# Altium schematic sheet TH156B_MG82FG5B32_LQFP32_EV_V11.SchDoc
size 279 x 203 mm; PageSetup: Record=PageOptions|CenterHorizontal=True|CenterVertical=True|PrintScale=0.98|XCorrection=1.00|YCorrection=1.00|PrintKind=0|BorderSize=5000000|LeftOffset=0|BottomOffset=0|Orientation=2|PaperLength=1000|PaperWidth=1000|Scale=100|PaperSource=7|PrintQuality=-4|MediaType=1|DitherType=10|PaperKind=A4 (210 x 297 mm)|PrintScaleMode=1
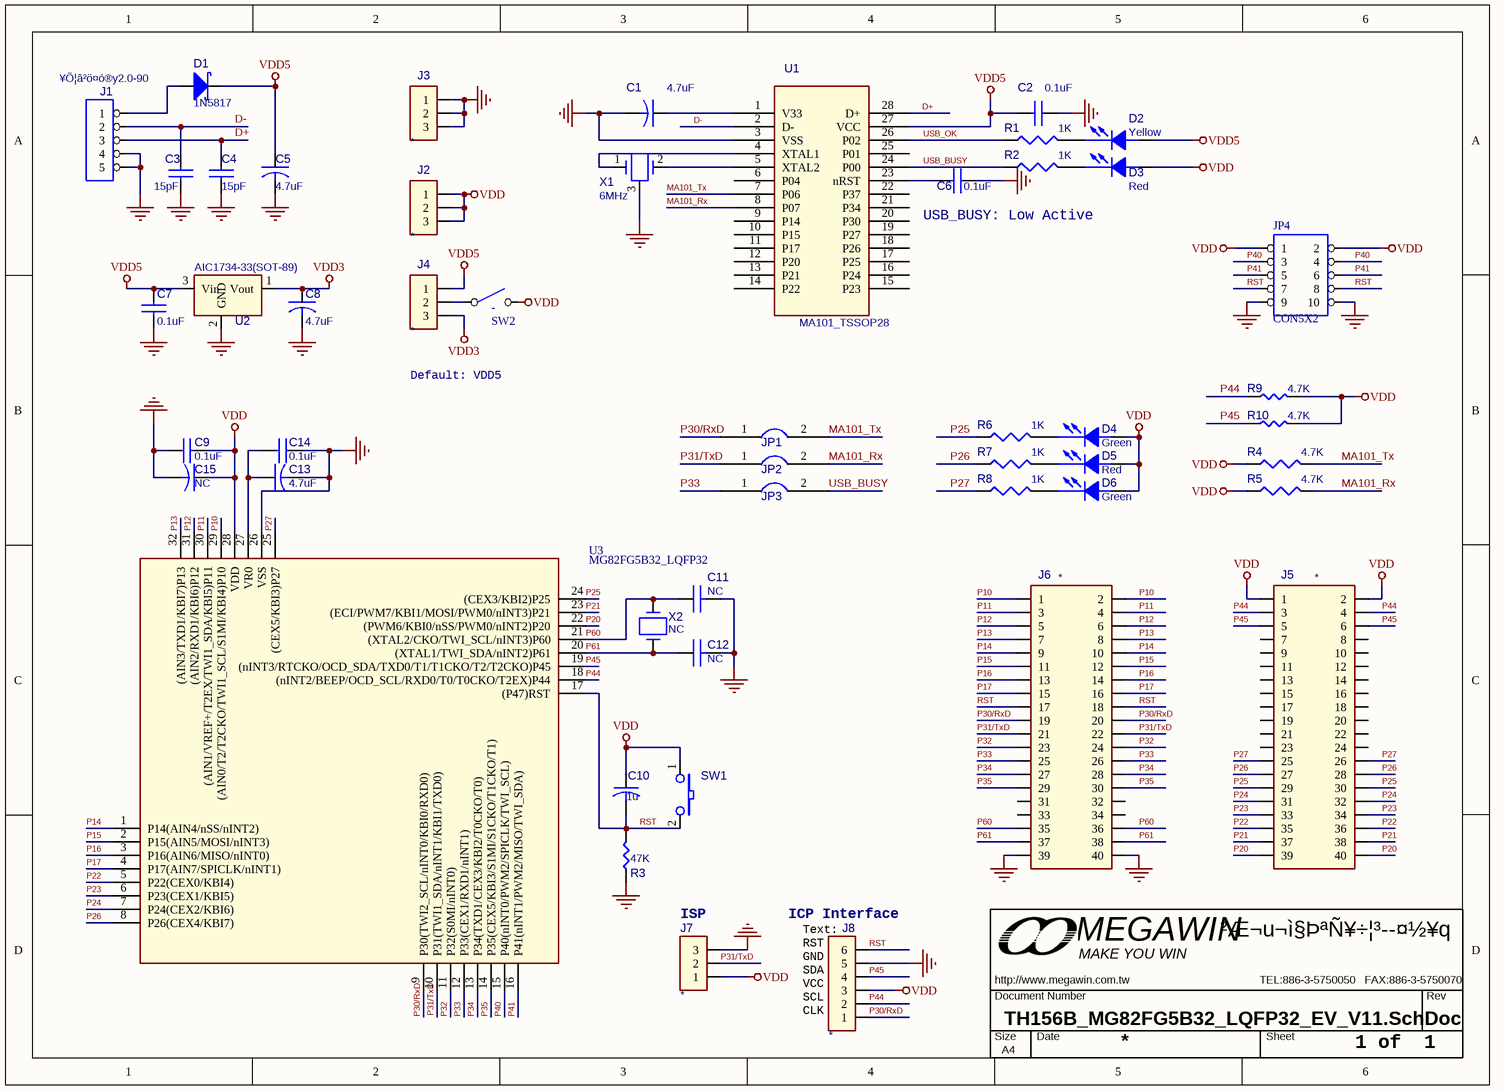
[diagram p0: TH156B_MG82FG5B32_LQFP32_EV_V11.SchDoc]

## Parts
C1  4.7uF  [0805C]
C2  0.1uF  [0805C]
C3  15pF  [0805C]
C4  15pF  [0805C]
C5  4.7uF  [1206C]
C6  0.1uF  [0805C]
C7  0.1uF  [0805C]
C8  4.7uF  [0805C]
C9  0.1uF  [0805C]
C10  1u  [0805C]
C11  NC  [0805C]
C12  NC  [0805C]
C13  4.7uF  [0805C]
C14  0.1uF  [0805C]
C15  NC  [0805C]
D1  1N5817  [D5817_SMD_1]
D2  Yellow  [0805D]
D3  Red  [0805D]
D4  Green  [0805D]
D5  Red  [0805D]
D6  Green  [0805D]
J1  ¥Õ¦â²ö¤ó®y2.0-90  [PC5p200_90]
J2  *  [PS3P254]
J3  *  [PS3P254]
J4  *  [JUMP3_SMD]
J5  *  [PS20X2P254]
J6  *  [PS20X2P254]
J7  *  [PS3P254f_90]
J8  *  [PS6P254F_90]
JP1  JUMPER2  [PS2P254]  (value not drawn)
JP2  JUMPER2  [PS2P254]  (value not drawn)
JP3  JUMPER2  [PS2P254]  (value not drawn)
JP4  CON5X2  [PS5X2P254]
MW1  OrgName: ²Æ¬u¬ì§ÞªÑ¥÷¦³­­¤½¥q  OrgAddr1: MEGAWIN  OrgAddr3: TEL:886-3-5750050   FAX:886-3-5750070  Page Size: A4  [MEGAWIN_T]  (hidden comment: MW-A4)  (no BOM)
R1  1K  [0805R]
R2  1K  [0805R]
R3  47K  [0805R]
R4  4.7K  [0805R]
R5  4.7K  [0805R]
R6  1K  [0805R]
R7  1K  [0805R]
R8  1K  [0805R]
R9  4.7K  [0805R]
R10  4.7K  [0805R]
SW1  SW TACT-SPST  [SW_T_2P]  (value not drawn)
SW2  -  [DIP2_SW]
U1  MA101_TSSOP28  [SSOP28_220P065]
U2  AIC1734-33(SOT-89)  [SOT89]
U3  MG82FG5B32_LQFP32  [QFP32_7X7p080]
X1  6MHz  [X3P]
X2  NC  [X49U]

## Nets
GND_POWER: C1.2 C2.1 C3.2 C4.2 C5.2 C6.1 C7.2 C8.2 C9.1 C11.2 C12.2 C13.2 C14.1 C15.2 J1.4 J1.5 J3.1 J3.2 J3.3 J6.39 J6.40 J7.3 J8.5 JP4.9 JP4.10 R3.1 U1.3(VSS) U2.2(GND) U3.26(VSS) X1.3
VDD: C9.2 C10.1(POS) C15.1 D3.1(ANODE) D4.1(ANODE) D5.1(ANODE) D6.1(ANODE) J2.1 J2.2 J2.3 J5.1 J5.2 J7.1 J8.3 JP4.1 JP4.2 R4.1 R5.1 R9.2 R10.2 SW1.1 SW2.2(NO) U3.28(VDD)
VDD3: C8.1 J4.3 U2.1(Vout)
VDD5: C2.2 C5.1 C7.1 D1.2(K) D2.1(ANODE) J4.1 U1.27(VCC) U2.3(Vin)
D+: C4.1 J1.3 U1.28(D+)
D-: C3.1 J1.2 U1.2(D-)
MA101_Rx: JP2.2 R5.2 U1.8(P07)
MA101_Tx: JP1.2 R4.2 U1.7(P06)
P10: J6.1 J6.2 U3.29((AIN0/T2/T2CKO/TWI1_SCL/S1MI/KBI4)P10)
P11: J6.3 J6.4 U3.30((AIN1/VREF+/T2EX/TWI1_SDA/KBI5)P11)
P12: J6.5 J6.6 U3.31((AIN2/RXD1/KBI6)P12)
P13: J6.7 J6.8 U3.32((AIN3/TXD1/KBI7)P13)
P14: J6.9 J6.10 U3.1(P14(AIN4/nSS/nINT2))
P15: J6.11 J6.12 U3.2(P15(AIN5/MOSI/nINT3))
P16: J6.13 J6.14 U3.3(P16(AIN6/MISO/nINT0))
P17: J6.15 J6.16 U3.4(P17(AIN7/SPICLK/nINT1))
P20: J5.39 J5.40 U3.22((PWM6/KBI0/nSS/PWM0/nINT2)P20)
P21: J5.37 J5.38 U3.23((ECI/PWM7/KBI1/MOSI/PWM0/nINT3)P21)
P22: J5.35 J5.36 U3.5(P22(CEX0/KBI4))
P23: J5.33 J5.34 U3.6(P23(CEX1/KBI5))
P24: J5.31 J5.32 U3.7(P24(CEX2/KBI6))
P25: J5.29 J5.30 R6.1 U3.24((CEX3/KBI2)P25)
P26: J5.27 J5.28 R7.1 U3.8(P26(CEX4/KBI7))
P27: J5.25 J5.26 R8.1 U3.25((CEX5/KBI3)P27)
P30/RxD: J6.19 J6.20 J8.1 JP1.1 U3.9(P30(TWI2_SCL/nINT0/KBI0/RXD0))
P31/TxD: J6.21 J6.22 J7.2 JP2.1 U3.10(P31(TWI1_SDA/nINT1/KBI1/TXD0))
P32: J6.23 J6.24 U3.11(P32(S0MI/nINT0))
P33: J6.25 J6.26 JP3.1 U3.12(P33(CEX1/RXD1/nINT1))
P34: J6.27 J6.28 U3.13(P34(TXD1/CEX3/KBI2/T0CKO/T0))
P35: J6.29 J6.30 U3.14(P35(CEX5/KBI3/S1MI/S1CKO/T1CKO/T1))
P40: JP4.3 JP4.4 U3.15(P40(nINT0/PWM2/SPICLK/TWI_SCL))
P41: JP4.5 JP4.6 U3.16(P41(nINT1/PWM2/MISO/TWI_SDA))
P44: J5.3 J5.4 J8.2 R9.1 U3.18((nINT2/BEEP/OCD_SCL/RXD0/T0/T0CKO/T2EX)P44)
P45: J5.5 J5.6 J8.4 R10.1 U3.19((nINT3/RTCKO/OCD_SDA/TXD0/T1/T1CKO/T2/T2CKO)P45)
P60: C11.1 J6.35 J6.36 U3.21((XTAL2/CKO/TWI_SCL/nINT3)P60) X2.2
P61: C12.1 J6.37 J6.38 U3.20((XTAL1/TWI_SDA/nINT2)P61) X2.1
RST: C10.2(NEG) J6.17 J6.18 J8.6 JP4.7 JP4.8 R3.2 SW1.2 U3.17((P47)RST)
USB_BUSY: JP3.2 R2.1 U1.24(P00)
USB_OK: R1.1 U1.26(P02)
NetC1_1: C1.1 U1.1(V33)
NetC6_2: C6.2 U1.23(nRST)
NetC13_1: C13.1 C14.2 U3.27(VR0)
NetD1_1: D1.1(A) J1.1
NetD2_2: D2.2(CATHODE) R1.2
NetD3_2: D3.2(CATHODE) R2.2
NetD4_2: D4.2(CATHODE) R6.2
NetD5_2: D5.2(CATHODE) R7.2
NetD6_2: D6.2(CATHODE) R8.2
NetJ4_2: J4.2 SW2.1(COMMON)
NetU1_4: U1.4(XTAL1) X1.1
NetU1_5: U1.5(XTAL2) X1.2

Not connected (* = marked no-connect by the designer): J5 7 8 9 10 11 12 13 14 15 16 17 18 19 20 21 22 23 24; J6 31 32 33 34; U1 6(P04) 9(P14) 10(P15) 11(P17) 12(P20) 13(P21) 14(P22) 15(P23) 16(P24) 17(P25) 18(P26) 19(P27) 20(P30) 21(P34) 22(P37) 25(P01)

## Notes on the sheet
- USB_BUSY: Low Active
- Default: VDD5
- (near J7) ISP
- (near J8) ICP Interface
- (near J8) Text:
  RST
  GND
  SDA
  VCC
  SCL
  CLK
- 1 of  1

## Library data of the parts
C1 C5 C8 C13 C15 = CAP
C2-C4 C6 C7 C9 C14 = CAP NP
C10 = C
C11 C12 = C NP
D1 = DIODE_ZD: Schottky Diode
D2-D6 = LED
J1 = CON5: Connector
J2-J4 J7 = CON3
J5 J6 = CON40A
J8 = CON6
R1 R2 R4-R8 = R_Dup1
R3 R9 R10 = R
SW2 = SW-2
U2 = AIC1734-33(SOT-89)_0
X1 = CRYSTAL_RC
X2 = CRYSTAL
